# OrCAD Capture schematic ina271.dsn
size B; title: INA271, Voltage Output, Unidirectional Measurement Current-Shunt Monitor; rev: 1.0; note: Datasheet:SBOS381C; note: Reference
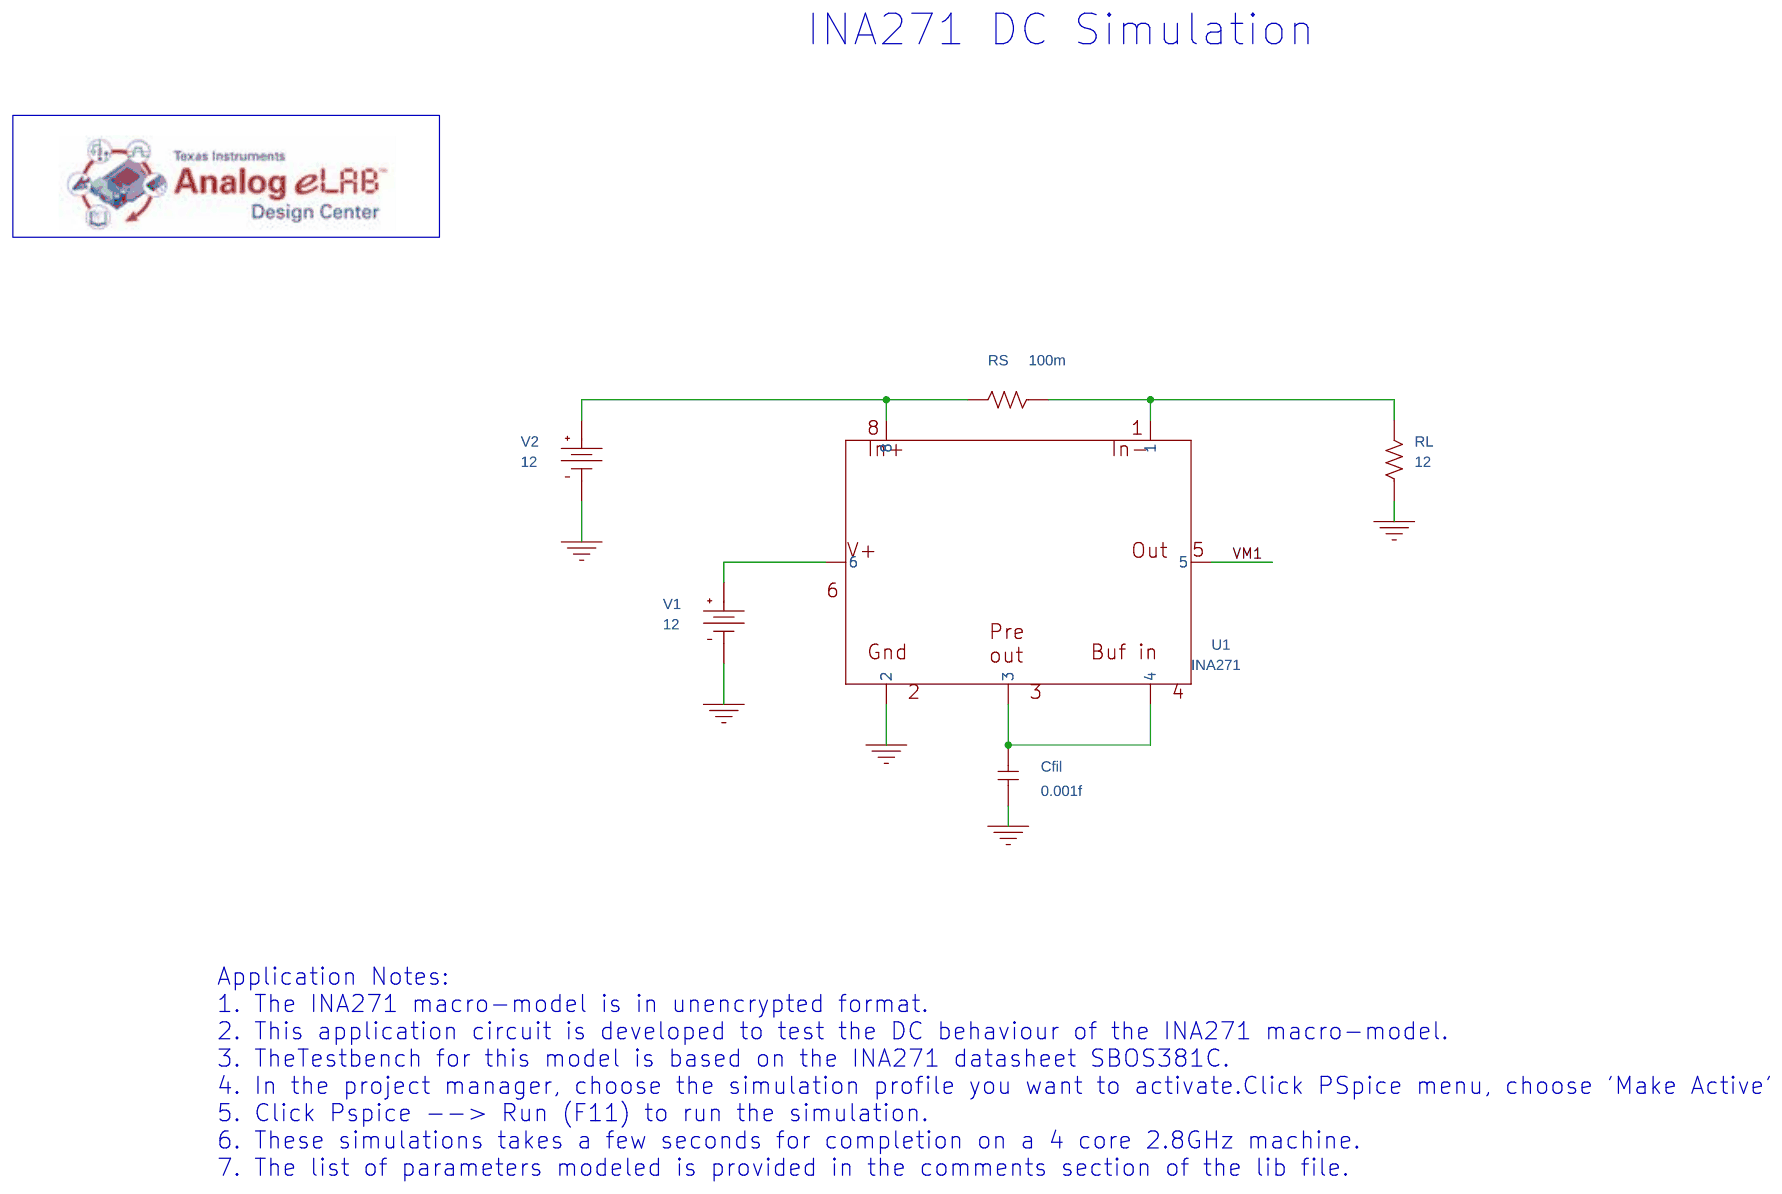
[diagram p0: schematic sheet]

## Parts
Cfil  0.001f  [RAD/CK05]
RL  12  [AX/RC05]
RS  100m  [AX/RC05]
U1  INA271
V1  VDC
V2  VDC

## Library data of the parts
Cfil = C
RL RS = R
U1 = INA271
V1 V2 = VDC: DC: 12

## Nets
0: Cfil.1 RL.1 U1.2 V1.1(-) V2.1(-)
VM1: U1.5
N14289172: RS.2 U1.8 V2.0(+)
N14289196: RL.2 RS.1 U1.1
N14289859: U1.6 V1.0(+)
N14290250: Cfil.2 U1.3 U1.4

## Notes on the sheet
- INA271 DC Simulation
- Application Notes:
  1. The INA271 macro-model is in unencrypted format.
  2. This application circuit is developed to test the DC behaviour of the INA271 macro-model.
  3. TheTestbench for this model is based on the INA271 datasheet SBOS381C.
  4. In the project manager, choose the simulation profile you want to activate.Click PSpice menu, choose 'Make Active'
  5. Click Pspice --> Run (F11) to run the simulation.
  6. These simulations takes a few seconds for completion on a 4 core 2.8GHz machine.
  7. The list of parameters modeled is provided in the comments section of the lib file.
